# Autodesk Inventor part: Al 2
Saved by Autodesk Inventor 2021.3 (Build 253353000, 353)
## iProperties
Created: 2024-03
Part Number: Al 2
Material: Generic
Document SubType Name: Modeling
Designer: AdminForWorker
Density: 1 g/cm^3
Appearance: Default
Title: Al 2
Author: AdminForWorker
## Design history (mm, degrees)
feature "Al 2"
body "Solid1"
